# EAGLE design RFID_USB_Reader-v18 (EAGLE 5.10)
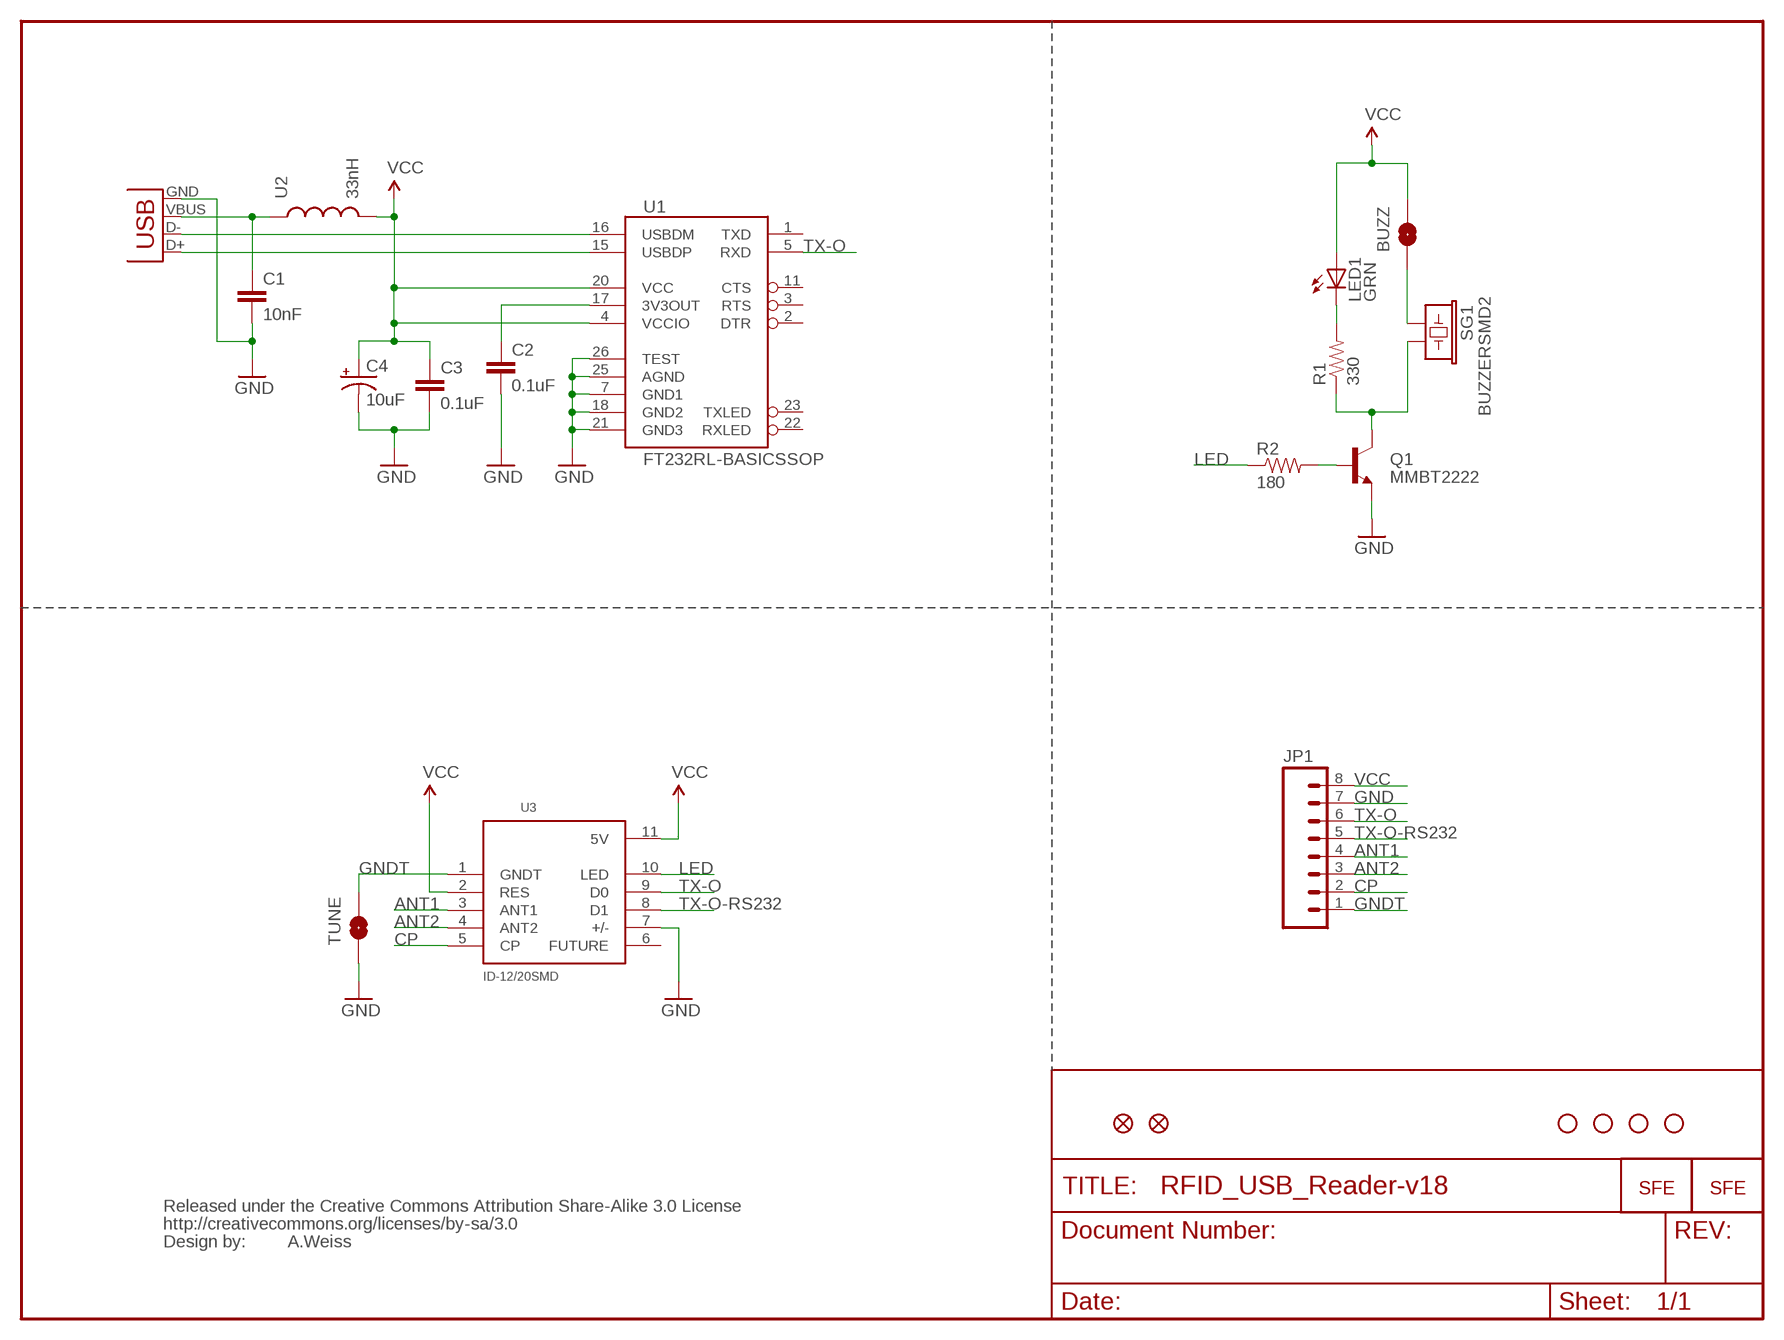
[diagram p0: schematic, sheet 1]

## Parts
BUZZ  buzz  SOLDERJUMPERNC2  [SJ_2S-NOTRACE]
C1  10nF  CAP0402-CAP  [0402-CAP]
C2  0.1uF  CAP0402-CAP  [0402-CAP]
C3  0.1uF  CAP0402-CAP  [0402-CAP]
C4  10uF  CAP_POL1206  [EIA3216]
JP1  M08  [1X08]
JP2  FIDUCIAL1X2  [FIDUCIAL-1X2]
JP3  FIDUCIAL1X2  [FIDUCIAL-1X2]
LED1  GRN  LED0603  [LED-0603]
Q1  MMBT2222  TRANSISTOR_NPNSOT23-3  [SOT23-3]
R1  330  RESISTOR0402-RES  [0402-RES]
R2  180  RESISTOR0402-RES  [0402-RES]
SG1  BUZZERSMD2  [BUZZER-CCV]
TUNE  SOLDERJUMPERNC2  [SJ_2S-NOTRACE]
U1  FT232RL-BASICSSOP  [SSOP28DB]
U2  33nH  INDUCTOR0402  [C0402]
U3  ID-12/20SMD  [ID-12_SMD]
U$1  LOGO-SFENEW  [SFE-NEW-WEBLOGO]
U$2  CREATIVE_COMMONS  [CREATIVE_COMMONS]
U$4  STAND-OFF  [STAND-OFF]
U$5  STAND-OFF  [STAND-OFF]
U$6  STAND-OFF  [STAND-OFF]
U$7  STAND-OFF  [STAND-OFF]
U$8  LOGO-SFESK  [SFE-LOGO-FLAME]
X1  USBSMD  [USB-MINIB]

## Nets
ANT1: JP1.4 U3.3(ANT1)
ANT2: JP1.3 U3.4(ANT2)
CP: JP1.2 U3.5(CP)
GND: C1.2 C2.2 C3.2 C4.C(-) JP1.7 Q1.2(E) TUNE.1 U1.7(GND1) U1.18(GND2) U1.21(GND3) U1.25(AGND) U1.26(TEST) U3.7(+/-) X1.GND
GNDT: JP1.1 TUNE.2 U3.1(GNDT)
LED: R2.1 U3.10(LED)
N$1: Q1.3(C) R1.1 SG1.-
N$2: U1.16(USBDM) X1.D-
N$3: C1.1 U2.1 X1.VBUS
N$4: U1.15(USBDP) X1.D+
N$5: BUZZ.1 SG1.+
N$6: C2.1 U1.17(3V3OUT)
N$7: LED1.C R1.2
N$8: Q1.1(B) R2.2
TX-O: JP1.6 U1.5(RXD) U3.9(D0)
TX-O-RS232: JP1.5 U3.8(D1)
VCC: BUZZ.2 C3.1 C4.A(+) JP1.8 LED1.A U1.4(VCCIO) U1.20(VCC) U2.2 U3.2(RES) U3.11(5V)
Unconnected: U1.1(TXD) U1.2(DTR) U1.3(RTS) U1.11(CTS) U1.22(RXLED) U1.23(TXLED) U3.6(FUTURE)

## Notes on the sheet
- A.Weiss

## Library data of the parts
BUZZ TUNE = SparkFun:SOLDERJUMPER: Solder Jumper
C1-C3 = SparkFun:CAP: Capacitor
C4 = SparkFun:CAP_POL: Capacitor Polarized
JP1 = SparkFun:M08: Header 8 Standard 8-pin 0.1" header. Use with straight break away headers (SKU : PRT-00116), right angle break away headers (PRT-00553), swiss pins (PRT-00743), machine pins (PRT-00117), and female headers (PRT-00115).
JP2 JP3 = SparkFun:FIDUCIAL: Fiducial Alignment Points
LED1 = SparkFun:LED: LEDs
Q1 = SparkFun:TRANSISTOR_NPN: Transistor NPN BJT configuration in SOT23 package. MMBT2222 is the common NPN we use. Double check BCE configuration again layout.
R1 R2 = SparkFun:RESISTOR: Resistor
SG1 = SparkFun:BUZZER: Buzzer 12mm
U1 = SparkFun:FT232RL-BASIC: USB UART This is the simplified version of the FT232RL unit. Only what you need, nothing you don't. Spark Fun Electronics SKU : COM-00650
U2 = SparkFun:INDUCTOR: Inductors
U3 = SparkFun:ID-12/20: ID2, ID12, and ID20 Package
U$1 U$8 = SparkFun:LOGO-SFE: Spark Fun Electronics PCB Logo
U$2 = SparkFun:CREATIVE_COMMONS
U$4-U$7 = SparkFun:STAND-OFF: Stand Off
X1 = SparkFun:USB: USB Connectors USB-B-PTH is fully proven SKU : PRT-00139 USB-miniB is fully proven SKU : PRT-00587 USB-A-PCB is untested. USB-A-H is throughly reviewed, but untested. Spark Fun Electronics SKU : PRT-00437 USB-B-SMT is throughly reviewed, but untested. Needs silkscreen touching up. USB-A-S has not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

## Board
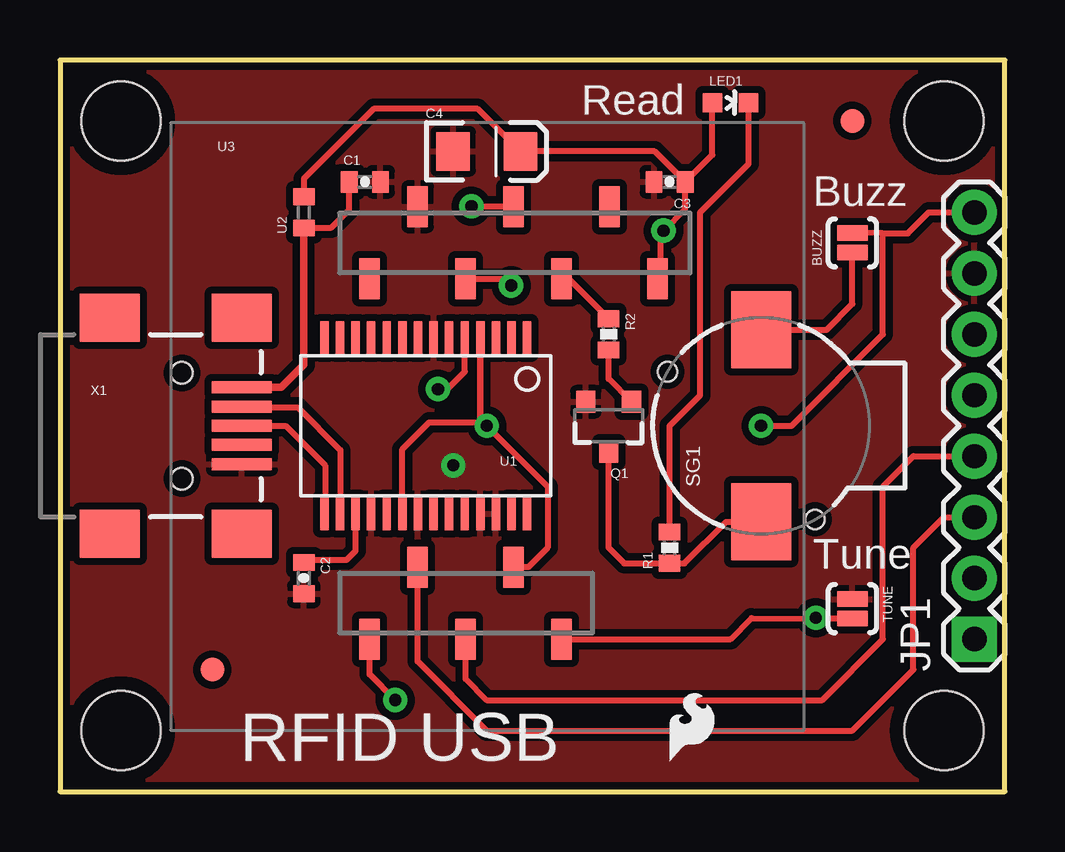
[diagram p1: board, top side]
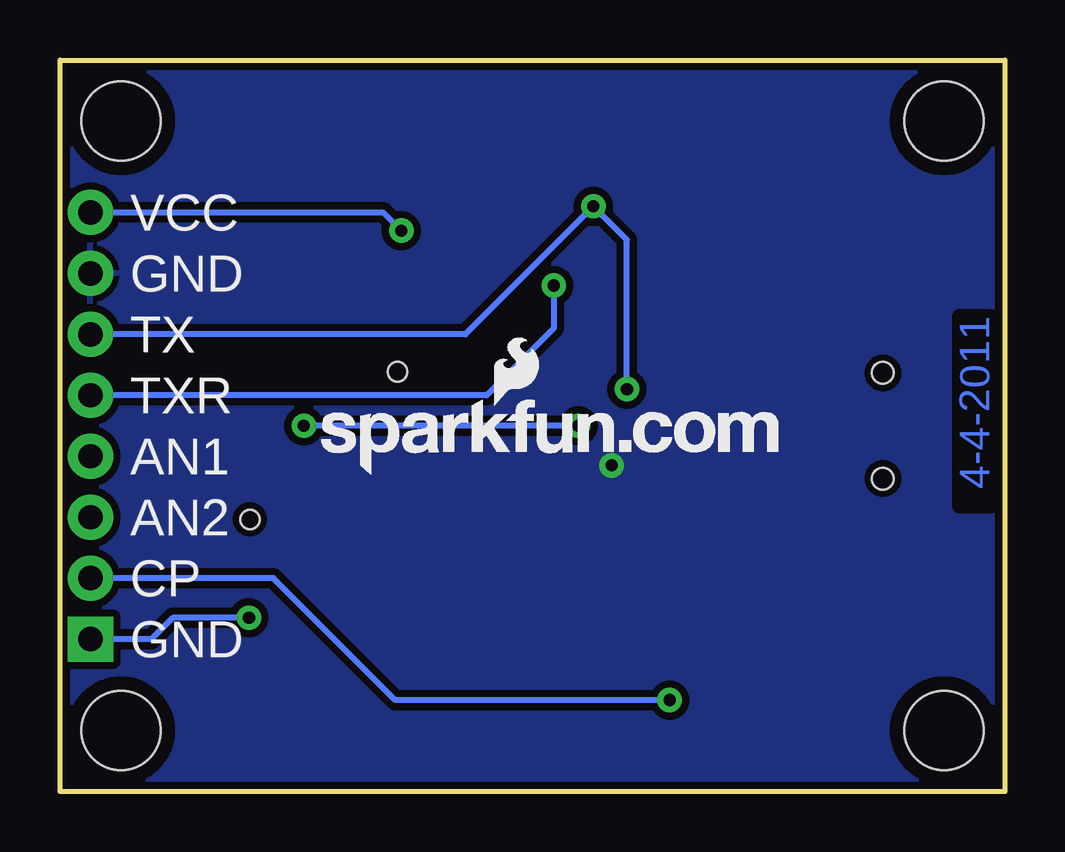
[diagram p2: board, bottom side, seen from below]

Size 39.37 x 30.48 mm. Coordinates in mm from the lower left corner, seen from the top.
Outline: 0,0 39.37,0 39.37,30.48 0,30.48 0,0
Copper layers (1*16): Top 0.035mm / dielectric 1.5mm / Bottom 0.035mm
Design rules "SparkFun": minimum track width 8mil, minimum drill 20mil, track to track 8mil, track to pad 8mil, pad to pad 8mil, via to via 8mil, smd to smd 8mil, copper to edge 8mil, drill to drill 8mil, minimum pad ring 12mil, minimum via ring 10mil, stop-mask expansion 4mil, vias tented up to drill 20mil, thermal gap 10mil

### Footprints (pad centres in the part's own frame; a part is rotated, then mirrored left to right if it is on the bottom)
SJ_2S-NOTRACE = smd 0.635 x 1.27: 1 -0.401,0; 2 0.413,0
0402-CAP = smd 0.7 x 0.9: 1 -0.65,0; 2 0.65,0
EIA3216 = smd 1.4 x 1.6: A 1.4,0; C -1.4,0
1X08 = drill 1.016 pad 1.88 square: 1 0,0 | drill 1.016 pad 1.88 round: 2 2.54,0; 3 5.08,0; 4 7.62,0; 5 10.16,0; 6 12.7,0; 7 15.24,0; 8 17.78,0
FIDUCIAL-1X2 = smd 1 x 1: 1 0,0
LED-0603 = smd 0.8 x 0.8: A 0,-0.75; C 0,0.75
SOT23-3 = smd 0.8 x 0.9: 1 -0.95,-1; 2 0.95,-1; 3 0,1.1
0402-RES = smd 0.7 x 0.9: 1 -0.65,0; 2 0.65,0
BUZZER-CCV = smd 3.2 x 2.5: + 4,0; - -4,0 | hole 0.8: -3.9,-2.25; 2.25,3.9
SSOP28DB = smd 0.348 x 1.397: 1 -4.225,-3.656; 2 -3.575,-3.656; 3 -2.925,-3.656; 4 -2.275,-3.656; 5 -1.625,-3.656; 6 -0.975,-3.656; 7 -0.325,-3.656; 8 0.325,-3.656; 9 0.975,-3.656; 10 1.625,-3.656; 11 2.275,-3.656; 12 2.925,-3.656; 13 3.575,-3.656; 14 4.225,-3.656; 15 4.225,3.656; 16 3.575,3.656; 17 2.925,3.656; 18 2.275,3.656; 19 1.625,3.656; 20 0.975,3.656; 21 0.325,3.656; 22 -0.325,3.656; 23 -0.975,3.656; 24 -1.625,3.656; 25 -2.275,3.656; 26 -2.925,3.656; 27 -3.575,3.656; 28 -4.225,3.656
C0402 = smd 0.7 x 0.9: 1 -0.65,0; 2 0.65,0
ID-12_SMD = smd 0.85 x 1.7: 1 16.248,3.81; 2 14.248,6.81; 3 12.248,3.81; 4 10.248,6.81; 5 8.248,3.81; 6 8.248,18.822; 7 10.248,21.822; 8 12.248,18.822; 9 14.248,21.822; 10 16.248,18.822; 11 20.248,18.822; NC 18.248,21.822
STAND-OFF = hole 3.302: 0,0
USB-MINIB = smd 2.5 x 0.5: D+ 2.5,0; D- 2.5,0.8; GND 2.5,-1.6; ID 2.5,-0.8; VBUS 2.5,1.6 | smd 2.5 x 2: GND@1 -3,-4.5; GND@2 -3,4.5; GND@3 2.5,4.5; GND@4 2.5,-4.5 | hole 0.9: 0,2.2; 0,-2.2

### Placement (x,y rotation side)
BUZZ  33.02,22.86 90 top
C1  12.7,25.4 0 top
C2  10.16,8.89 270 top
C3  25.4,25.4 180 top
C4  17.78,26.67 0 top
JP1  38.1,6.35 90 top
JP2  6.35,5.08 0 top
JP3  33.02,27.94 0 top
LED1  27.94,28.7 270 top
Q1  22.86,15.24 180 top
R1  25.4,10.16 90 top
R2  22.86,19.05 270 top
SG1  29.21,15.24 90 top
TUNE  33.02,7.62 270 top
U1  15.24,15.24 180 top
U2  10.16,24.13 90 top
U3  4.65,2.54 0 top
U$1  28.5,13.21 0 bottom
U$2  not placed on the board
U$4  2.54,27.94 0 top
U$5  2.54,2.54 0 top
U$6  36.83,27.94 0 top
U$7  36.83,2.54 0 top
U$8  25.4,1.27 0 top
X1  5.08,15.24 0 top

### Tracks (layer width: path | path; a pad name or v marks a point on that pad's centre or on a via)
ANT1
  Top 0.254: JP1.4 35.56,13.97 34.29,12.7 34.29,6.35 31.75,3.81 17.78,3.81 16.9,4.69 U3.3
ANT2
  Top 0.254: JP1.3 36.83,11.43 35.56,10.16 35.56,5.08 33.02,2.54 17.78,2.54 14.9,5.42 U3.4
CP  (via drill 0.51)
  Top 0.254: v13.97,3.81 12.9,4.88 U3.5
  Bottom 0.254: JP1.2 30.48,8.89 25.4,3.81 v13.97,3.81
GND  (via drill 0.51)
  other vias: 16.38,13.59
  pour Top (isolate 0.305): 0,30.48 0,0 39.37,0 39.37,30.48
  pour Bottom (isolate 0.305): 0,30.48 0,0 39.37,0 39.37,30.48
GNDT  (via drill 0.51)
  Top 0.254: U3.1 27.94,6.35 28.81,7.22 TUNE.2 31.52,7.22 v31.5,7.24
  Bottom 0.254: v31.5,7.24 34.67,7.24 35.56,6.35 JP1.1
LED
  Top 0.254: R2.1 21.2,21.36 U3.10
N$1
  Top 0.254: 22.73,13.97 22.86,14.1 Q1.3 22.86,10.16 23.51,9.51 R1.1 26.02,9.51 27.75,11.24 SG1.-
N$2
  Top 0.254: X1.D- 7.62,16 9.91,16 11.68,14.22 11.68,11.56 | 11.68,11.56 11.68,11.43 | 11.68,11.56 U1.16
N$3
  Top 0.254: 10.05,23.48 10.16,23.37 U2.1 10.16,23.5 11.3,23.5 12.05,24.24 C1.1
  Top 0.305: X1.VBUS 9.22,16.84 10.16,17.78 U2.1
N$4
  Top 0.254: X1.D+ 9.4,15.24 11.05,13.59 11.05,11.56 11.04,11.56 U1.15
N$5
  Top 0.254: BUZZ.1 33.02,20.32 31.94,19.24 SG1.+
N$6
  Top 0.254: U1.17 12.31,10.03 11.94,9.65 10.16,9.65 C2.1
N$7
  Top 0.254: 28.7,28.7 LED1.C 28.69,26.15 26.67,24.13 26.67,16.51 25.4,15.24 R1.2
N$8
  Top 0.254: Q1.1 22.86,17.19 R2.2
TX-O  (via drill 0.51)
  Top 0.254: U3.9 18.88,24.38 v17.14,24.38 | v15.75,16.76 16.13,16.76 16.86,17.5 U1.5
  Bottom 0.254: v15.75,16.76 15.75,22.99 v17.14,24.38 22.48,19.05 JP1.6
TX-O-RS232  (via drill 0.51)
  Top 0.254: U3.8 18.52,21.36 v18.8,21.08
  Bottom 0.254: v18.8,21.08 18.8,19.3 21.59,16.51 JP1.5
VCC  (via drill 0.51)
  Top 0.254: LED1.A 27.18,28.7 27.18,26.53 C3.1 | 17.52,15.38 U1.4 17.52,15.51 v17.78,15.24 | 10.16,24.77 U2.2 10.16,25.53 13.08,28.45 17.4,28.45 C4.A 24.78,26.67 C3.1 | 17.52,15.38 17.64,15.38 v17.78,15.24 | U1.20 14.27,14.27 15.38,15.38 17.52,15.38 | v17.78,15.24 20.32,12.7 20.32,10.16 19.51,9.35 U3.2 | U3.11 25.02,21.48 25.02,23.24 v25.15,23.37 26.05,24.27 C3.1 | JP1.8 36.2,24.13 35.33,23.26 34.29,23.26 | 34.29,23.26 BUZZ.2 | v29.21,15.24 30.48,15.24 34.29,19.05 34.29,23.26
  Bottom 0.254: v25.15,23.37 25.91,24.13 JP1.8 | v17.78,15.24 v29.21,15.24

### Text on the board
Bottom: 4-4-2011
tPlace: Read | Buzz | Tune | RFID USB
bPlace: VCC | GND | TX | TXR | AN1 | AN2 | CP | GND
Reference: before lbr update, the jumper center point was a little different on v14, reference drawing shows exactly where it is on v14 - plewis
